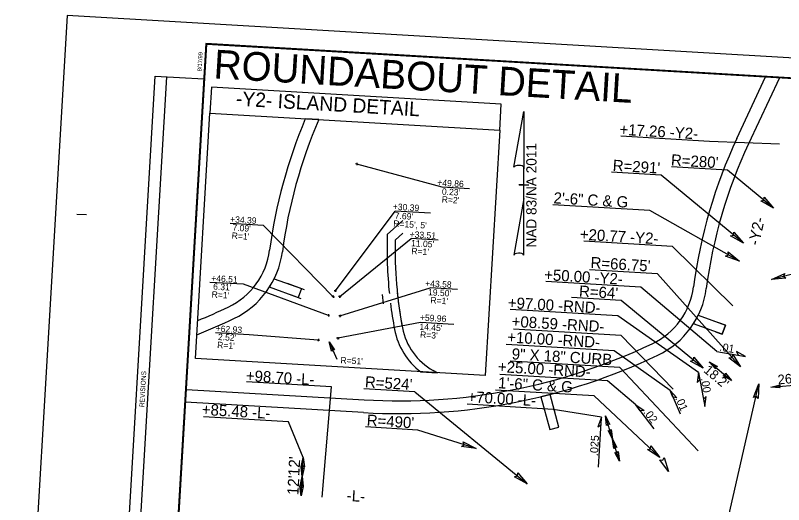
# Model space of a CAD drawing. Extents: x 2012744 to 2013625, y 444638 to 445237.
# Drawn here: x 2012743.6 to 2013223.7, y 444930.6 to 445236.8 of the extents above; entities that cross this region are included whole.
import ezdxf

# ---------------------------------------------------------------- set-up
doc = ezdxf.new("R2010")
doc.units = 0
for name, color, linetype in [('Old_Level_1', 7, 'Continuous'), ('Old_Level_10', 7, 'Continuous'), ('Prop Conc 4in Sidewalk', 7, 'Continuous'), ('Prop Dimension', 7, 'Continuous'), ('Prop Dimension Text', 7, 'Continuous'), ('Prop North Arrow NAD83 for Plan Sheets CELL', 7, 'Continuous'), ('Prop Shade Medium', 7, 'Continuous'), ('Prop Superelevation  Arrow CELL', 7, 'Continuous'), ('Prop Superelevation Label', 7, 'Continuous'), ('Prop Terminator CELL', 7, 'Continuous'), ('Sheet Block Revision CELL', 7, 'Continuous'), ('Sheet Clip Boundary CELL', 7, 'Continuous'), ('Sheet Plan And Profile CELL', 7, 'Continuous'), ('Sheet Plot Border Outside CELL', 7, 'Continuous')]:
    doc.layers.add(name, color=color, linetype=linetype)

msp = doc.modelspace()

# ---------------------------------------------------------------- linework, layer by layer
at = {"layer": 'Old_Level_1'}
for points in [[(2012865.22, 445175.54), (2013046.27, 445164.87), (2013047.24, 445181.2), (2012866.19, 445191.87)], [(2012865.22, 445175.54), (2013046.27, 445164.87), (2013037.11, 445011.37), (2012856.18, 445022.04)]]:
    msp.add_lwpolyline(points, close=True, dxfattribs=at)
at = {"layer": 'Prop Conc 4in Sidewalk'}
for p, q in [((2012924.35, 445065.12), (2012913.57, 445069.04)), ((2012922.29, 445059.48), (2012916.22, 445061.69))]:
    msp.add_line(p, q, dxfattribs=at)
for centre, radius, start, end in [((2013249.36, 445090.83), 268.5, 185.8936, 190.6549), ((2013249.36, 445090.83), 273.5, 187.1616, 190.6549), ((2013023.33, 445048.31), 38.5, 190.6549, 241.0711)]:
    msp.add_arc(centre, radius, start, end, dxfattribs=at)
at = {"layer": 'Prop Dimension'}
for p, q in [((2013177.31, 445157.92), (2013122.04, 445161.18)), ((2013010.35, 445129.33), (2012956.94, 445143.77)), ((2013188.68, 445139.96), (2013153.65, 445142.03)), ((2013147.07, 445136.87), (2013116.07, 445138.7)), ((2013027.37, 445128.32), (2013010.35, 445129.33)), ((2013140.05, 445114.63), (2013079.38, 445118.21)), ((2012943.61, 445064.49), (2012980.9, 445114.25)), ((2013002.96, 445112.95), (2012980.9, 445114.25)), ((2013196.1, 445083.05), (2013140.05, 445114.63)), ((2012898.72, 445105.32), (2012877.76, 445106.55)), ((2012942.24, 445060.77), (2012898.72, 445105.32)), ((2012946.3, 445060.82), (2012990.86, 445097.07)), ((2013007.88, 445096.07), (2012990.86, 445097.07)), ((2013154.21, 445092.18), (2013098.94, 445095.44)), ((2013285.84, 445089.12), (2013216.04, 445071.62)), ((2013144.93, 445075.13), (2013102.29, 445077.64)), ((2012886.17, 445068.5), (2012865.21, 445069.73)), ((2013134.55, 445066.74), (2013075.06, 445070.25)), ((2012939.27, 445049.09), (2012886.17, 445068.5)), ((2012946.44, 445048.74), (2013002.78, 445066.29)), ((2013019.8, 445065.29), (2013002.78, 445066.29)), ((2013122.16, 445058.44), (2013091.16, 445060.27)), ((2013120.13, 445048.71), (2013052.78, 445052.68)), ((2012996.72, 445044.68), (2012945.12, 445034.71)), ((2013017.68, 445043.45), (2012996.72, 445044.68)), ((2012889.65, 445036.94), (2012868.68, 445038.17)), ((2012932.89, 445033.62), (2012889.65, 445036.94)), ((2013122.22, 445036.51), (2013054.85, 445040.48)), ((2012939.67, 445032.45), (2012944.53, 445021.69)), ((2013117.77, 445026.79), (2013050.4, 445030.76)), ((2013121.35, 445016.42), (2013052.8, 445020.46)), ((2013177.2, 445020.08), (2013191.14, 445008.35)), ((2013113.63, 445008.18), (2013046.25, 445012.15)), ((2013121.35, 445016.42), (2013170.22, 444964.22)), ((2012941.18, 445004.29), (2012888.11, 445007.42)), ((2012935.33, 444935.42), (2012941.18, 445004.29)), ((2012993.31, 445001.15), (2012961.38, 445003.03)), ((2013105.33, 444998.67), (2013043.63, 445002.31)), ((2013168.27, 444830.65), (2013208.29, 445006.14)), ((2013215.66, 445004.13), (2013241.81, 445006.46)), ((2012993.31, 445001.15), (2013063.53, 444943.63)), ((2013146.23, 444960.14), (2013105.33, 444998.67)), ((2013079.64, 444990.26), (2013026.04, 444993.42)), ((2012914.27, 444982.56), (2012861.2, 444985.69)), ((2013116.76, 444971.71), (2013112.3, 444986.13)), ((2012923.55, 444960.15), (2012914.27, 444982.56)), ((2012995.09, 444977.35), (2012962.33, 444979.28)), ((2013031.55, 444965.74), (2012995.09, 444977.35)), ((2013121.03, 444957.92), (2013116.76, 444971.71)), ((2012922.84, 444948.17), (2012923.55, 444960.15)), ((2012922.14, 444936.19), (2012922.84, 444948.17))]:
    msp.add_line(p, q, dxfattribs=at)
at = {"layer": 'Prop Dimension Text'}
for p, q in [((2013221.16, 445156.24), (2013177.31, 445157.92)), ((2012956.94, 445143.77), (2012956.19, 445143.81)), ((2012956.99, 445144.51), (2012956.9, 445143.02)), ((2012956.94, 445143.77), (2012957.69, 445143.72)), ((2013198.55, 445094.22), (2013147.07, 445136.87)), ((2013217.44, 445116.14), (2013188.68, 445139.96)), ((2013191.92, 445054.96), (2013154.21, 445092.18)), ((2013196.73, 445016.84), (2013144.93, 445075.13)), ((2012943.65, 445065.24), (2012943.56, 445063.74)), ((2013181.94, 445026.49), (2013134.55, 445066.74)), ((2012942.24, 445060.77), (2012941.49, 445060.82)), ((2012942.29, 445061.52), (2012942.2, 445060.02)), ((2012942.24, 445060.77), (2012942.99, 445060.73)), ((2012943.61, 445064.49), (2012942.86, 445064.53)), ((2012943.61, 445064.49), (2012944.36, 445064.45)), ((2012946.3, 445060.82), (2012945.55, 445060.86)), ((2012946.34, 445061.57), (2012946.25, 445060.07)), ((2012946.3, 445060.82), (2012947.05, 445060.77)), ((2013173.42, 445015.97), (2013122.16, 445058.44)), ((2012939.27, 445049.09), (2012938.52, 445049.13)), ((2012939.31, 445049.84), (2012939.22, 445048.34)), ((2012939.27, 445049.09), (2012940.02, 445049.05)), ((2012946.44, 445048.74), (2012945.69, 445048.79)), ((2012946.48, 445049.49), (2012946.39, 445047.99)), ((2012946.44, 445048.74), (2012947.19, 445048.7)), ((2013170.51, 445013.24), (2013120.13, 445048.71)), ((2013154.65, 445003), (2013122.22, 445036.51)), ((2012932.89, 445033.62), (2012932.14, 445033.66)), ((2012932.94, 445034.36), (2012932.85, 445032.87)), ((2012932.89, 445033.62), (2012933.64, 445033.57)), ((2012945.12, 445034.71), (2012944.37, 445034.75)), ((2012945.16, 445035.45), (2012945.07, 445033.96)), ((2012945.12, 445034.71), (2012945.87, 445034.66)), ((2013152.69, 445002.12), (2013117.77, 445026.79)), ((2013131.25, 444993.12), (2013113.63, 445008.18)), ((2013109.87, 444985.3), (2013079.64, 444990.26))]:
    msp.add_line(p, q, dxfattribs=at)
at = {"layer": 'Prop North Arrow NAD83 for Plan Sheets CELL'}
for p, q in [((2013055.17, 445141.81), (2013061.32, 445176.58)), ((2013061.36, 445176.58), (2013061.32, 445176.58)), ((2013061.36, 445176.58), (2013061.32, 445176.58)), ((2013061.36, 445176.58), (2013061.36, 445140.73)), ((2013061.35, 445122.13), (2013061.36, 445141.78)), ((2013061.36, 445140.73), (2013061.36, 445141.74)), ((2013058.36, 445130.83), (2013058.32, 445130.83)), ((2013061.02, 445130.83), (2013058.36, 445130.83)), ((2013058.39, 445130.83), (2013064.39, 445130.83)), ((2013061.35, 445122.13), (2013055.09, 445086.69)), ((2013061.39, 445086.84), (2013061.35, 445122.13))]:
    msp.add_line(p, q, dxfattribs=at)
for centre, start_param, end_param in [((2013058.27, 445141.44), 0.216388, 2.908219), ((2013058.27, 445086.56), 0.201328, 3.141593)]:
    msp.add_ellipse(centre, major_axis=(3.17, -0.02), ratio=0.461098, start_param=start_param, end_param=end_param, dxfattribs=at)
at = {"layer": 'Prop Shade Medium'}
for p, q in [((2013194.49, 445159.8), (2013212.46, 445198.27)), ((2013221.05, 445197.76), (2013201.74, 445156.41)), ((2012933.31, 445171.53), (2012924.82, 445172.03)), ((2012985.73, 445108.41), (2012976.01, 445099.74)), ((2012980.91, 445096.05), (2012985.8, 445100.47)), ((2012902.41, 445066.72), (2012905.39, 445072.02)), ((2012905.39, 445072.02), (2012922.51, 445065.79)), ((2012920.45, 445060.15), (2012902.41, 445066.72)), ((2012922.47, 445065.8), (2012920.41, 445060.17)), ((2012972.85, 445062.19), (2012973.53, 445056.23)), ((2013167.32, 445043.81), (2013170.31, 445049.11)), ((2013170.31, 445049.11), (2013187.43, 445042.87)), ((2013187.38, 445042.89), (2013178.49, 445046.13)), ((2013185.37, 445037.24), (2013167.32, 445043.81)), ((2013185.33, 445037.25), (2013187.38, 445042.89)), ((2013187.38, 445042.89), (2013185.33, 445037.25)), ((2013181.14, 445038.78), (2013185.33, 445037.25)), ((2012996.91, 445013.74), (2013007.39, 445013.13)), ((2013007.39, 445013.13), (2013004.7, 445014.61)), ((2012850.01, 444994.79), (2012850.48, 445002.78)), ((2012850.48, 445002.78), (2012961.67, 444996.22)), ((2013077.77, 444999.64), (2013071.95, 444998.18)), ((2013071.95, 444998.18), (2013077.53, 444977.62)), ((2013083.32, 444979.2), (2013077.77, 444999.64)), ((2012961.2, 444988.24), (2012850.01, 444994.79)), ((2013077.54, 444977.62), (2013083.32, 444979.2))]:
    msp.add_line(p, q, dxfattribs=at)
for centre, radius, start, end in [((2013215.86, 445048.95), 316, 157.0774, 172.5631), ((2013215.86, 445048.95), 308, 156.548, 172.5631), ((2013480.78, 445026.04), 316, 154.9563, 172.5631), ((2013480.78, 445026.04), 308, 154.9563, 172.5631), ((2013249.36, 445090.83), 273.5, 178.1336, 185.9047), ((2013249.36, 445090.83), 268.5, 178.8864, 190.6549), ((2012856.91, 445095.81), 46, 295.4749, 352.5631), ((2012856.91, 445095.81), 54, 295.4749, 352.5631), ((2013121.83, 445072.89), 46, 295.4749, 352.5631), ((2013121.83, 445072.89), 54, 295.4749, 352.5631), ((2013249.36, 445090.83), 273.5, 187.1616, 190.6549), ((2012718.41, 445386.5), 368, 292.2205, 295.4749), ((2012718.41, 445386.5), 376, 291.638, 295.4749), ((2013023.33, 445048.31), 38.5, 190.6549, 241.0711), ((2013023.33, 445048.31), 43.5, 190.6549, 232.6121), ((2012983.33, 445363.58), 368, 266.6264, 295.4749), ((2012983.33, 445363.58), 376, 266.6264, 295.4749)]:
    msp.add_arc(centre, radius, start, end, dxfattribs=at)
at = {"layer": 'Prop Superelevation  Arrow CELL'}
for points in [[(2013199.91, 445023.41), (2013194.34, 445026.39), (2013195.35, 445024.19)], [(2013170.51, 445013.24), (2013169.65, 445006.98), (2013171.36, 445008.7)], [(2013152.69, 445002.12), (2013156.88, 444997.38), (2013154.5, 444997.86)], [(2013174.47, 444992.11), (2013175.33, 444998.38), (2013173.61, 444996.66)], [(2013131.25, 444993.12), (2013136.48, 444989.56), (2013134.06, 444989.44)], [(2013109.87, 444985.3), (2013107.52, 444979.43), (2013109.6, 444980.68)]]:
    msp.add_lwpolyline(points, close=True, dxfattribs=at)
at = {"layer": 'Prop Superelevation Label'}
for p, q in [((2013181.94, 445026.49), (2013199.91, 445023.41)), ((2013170.51, 445013.24), (2013174.47, 444992.11)), ((2013152.69, 445002.12), (2013158.94, 444987.42)), ((2013142.78, 444978.02), (2013131.25, 444993.12)), ((2013108.03, 444954.08), (2013109.87, 444985.3))]:
    msp.add_line(p, q, dxfattribs=at)
at = {"layer": 'Prop Terminator CELL'}
for points in [[(2013211.5, 445123.07), (2013217.44, 445116.14), (2013209.45, 445120.68), (2013211.36, 445121.18)], [(2013192.61, 445101.16), (2013198.55, 445094.22), (2013190.56, 445098.76), (2013192.47, 445099.26)], [(2013189.02, 445088.82), (2013196.1, 445083.05), (2013187.43, 445086.1), (2013189.21, 445086.93)], [(2013225.14, 445072.31), (2013216.04, 445071.62), (2013224.43, 445075.37), (2013223.7, 445073.54)], [(2012941.16, 445026.7), (2012939.67, 445032.45), (2012943.04, 445027.51), (2012941.79, 445027.77)], [(2013167.48, 445022.91), (2013173.42, 445015.97), (2013165.43, 445020.52), (2013167.34, 445021.01)], [(2013191.91, 445024.6), (2013196.73, 445016.84), (2013189.52, 445022.54), (2013191.48, 445022.74)], [(2013181.03, 445015.55), (2013177.2, 445020.08), (2013182.37, 445017.09), (2013181.13, 445016.78)], [(2013187.32, 445012.89), (2013191.14, 445008.35), (2013185.97, 445011.34), (2013187.21, 445011.66)], [(2013204.78, 444997.71), (2013208.29, 445006.14), (2013207.84, 444996.96), (2013206.53, 444998.44)], [(2013221.58, 445003.65), (2013215.66, 445004.13), (2013221.43, 445005.69), (2013220.78, 445004.59)], [(2013113.07, 444980.25), (2013112.3, 444986.13), (2013115.04, 444980.82), (2013113.82, 444981.23)], [(2013116, 444977.6), (2013116.76, 444971.71), (2013114.03, 444977.03), (2013115.25, 444976.62)], [(2013023.44, 444969.95), (2013031.55, 444965.74), (2013022.44, 444966.96), (2013024.02, 444968.14)], [(2013117.53, 444965.83), (2013116.76, 444971.71), (2013119.5, 444966.4), (2013118.28, 444966.81)], [(2013120.27, 444963.8), (2013121.03, 444957.92), (2013118.3, 444963.23), (2013119.52, 444962.82)], [(2013140.75, 444967.44), (2013146.23, 444960.14), (2013138.55, 444965.18), (2013140.48, 444965.56)], [(2012922.2, 444954.37), (2012923.55, 444960.15), (2012924.24, 444954.22), (2012923.25, 444955.03)], [(2013149.07, 444960.16), (2013151.75, 444951.42), (2013146.24, 444958.78), (2013148.18, 444958.47)], [(2012924.19, 444953.95), (2012922.84, 444948.17), (2012922.15, 444954.11), (2012923.14, 444953.3)], [(2013057.55, 444950.54), (2013063.53, 444943.63), (2013055.52, 444948.13), (2013057.42, 444948.64)], [(2012921.49, 444942.39), (2012922.84, 444948.17), (2012923.53, 444942.24), (2012922.54, 444943.05)], [(2012923.49, 444941.97), (2012922.14, 444936.19), (2012921.44, 444942.13), (2012922.44, 444941.32)]]:
    msp.add_lwpolyline(points, close=True, dxfattribs=at)
at = {"layer": 'Sheet Block Revision CELL'}
msp.add_line((2012815.07, 444803.74), (2012838.34, 445198.38), dxfattribs=at)
msp.add_lwpolyline([(2012807.81, 444804.17), (2012831.07, 445198.81), (2012861.3, 445197.03), (2012838.03, 444802.39)], close=True, dxfattribs=at)
at = {"layer": 'Sheet Clip Boundary CELL'}
for points in [[(2013605.95, 445084.18), (2013506.09, 445090.07), (2013509.49, 445147.63), (2013409.64, 445153.51), (2013411.6, 445186.8), (2012862.6, 445219.16), (2012831.71, 444695.07), (2013580.41, 444650.94)], [(2012832.37, 444695.56), (2012863.22, 445218.85), (2013411.41, 445186.54), (2013409.45, 445153.34), (2013509.31, 445147.45), (2013505.92, 445089.85), (2013605.86, 445083.96), (2013580.34, 444651.05)]]:
    msp.add_lwpolyline(points, close=True, dxfattribs=at)
at = {"layer": 'Sheet Plan And Profile CELL'}
msp.add_line((2012781.93, 445112.48), (2012788.17, 445112.11), dxfattribs=at)
msp.add_lwpolyline([(2013611.3, 445175.03), (2012862.6, 445219.16), (2012831.71, 444695.07), (2013580.41, 444650.94)], close=True, dxfattribs=at)
at = {"layer": 'Sheet Plot Border Outside CELL'}
msp.add_lwpolyline([(2012743.62, 444687.74), (2013592.15, 444637.73), (2013624.51, 445186.77), (2012775.99, 445236.79)], close=True, dxfattribs=at)

# ---------------------------------------------------------------- texts
at = {"layer": 'Old_Level_10'}
for s, p in [('+49.86', (2013007.21, 445130.24)), ("0.23'", (2013010.06, 445124.63)), ("R=2'", (2013009.97, 445119.68)), ('+30.39', (2012979.4, 445115.2)), ("7.69'", (2012980.6, 445109.55)), ('+34.39', (2012877.74, 445107.28)), ("R=15', 5'", (2012979.67, 445104.58)), ("7.09'", (2012879.19, 445102.05)), ("R=1'", (2012878.71, 445097.03)), ('+33.51', (2012989.9, 445097.86)), ("11.05'", (2012990.8, 445092.36)), ("R=1'", (2012990.96, 445087.4)), ('+46.51', (2012865.94, 445070.42)), ('+43.58', (2012999.63, 445067.2)), ("6.31'", (2012867.12, 445065.2)), ("19.50'", (2013001.39, 445061.66)), ("R=1'", (2012866.16, 445060.2)), ("R=1'", (2013002.88, 445056.62)), ('+59.96', (2012996.33, 445045.86)), ('+62.93', (2012868.72, 445038.9)), ("14.45'", (2012995.99, 445039.97)), ("2.52'", (2012870.12, 445033.67)), ("R=3'", (2012996.41, 445035.12)), ("R=1'", (2012869.63, 445028.64)), ("R=51'", (2012946.68, 445019.1))]:
    msp.add_text(s, height=4, rotation=356.6264, dxfattribs=at).set_placement(p)
at = {"layer": 'Prop Dimension'}
for s, height, rotation, p in [('ROUNDABOUT DETAIL', 18, 356.6264, (2012867.2, 445197.41)), ('-Y2- ISLAND DETAIL', 9, 356.6264, (2012881.27, 445180.34)), ('-Y2- ', 7, 77.6645, (2013208.25, 445092.43)), ('-L-', 7, 356.6264, (2012950.54, 444932.96))]:
    msp.add_text(s, height=height, rotation=rotation, dxfattribs=at).set_placement(p)
at = {"layer": 'Prop Dimension Text'}
for s, height, rotation, p in [('+17.26 -Y2-', 7, 356.6264, (2013120.96, 445162.09)), ("R=291'", 7, 356.6264, (2013116.75, 445139.51)), ("R=280'", 7, 356.6264, (2013153.15, 445142.91)), ('2\'-6" C & G', 7, 356.6264, (2013079.76, 445119.18)), ('+20.77 -Y2-', 7, 356.6264, (2013096.19, 445096.45)), ("R=66.75'", 7, 356.6264, (2013102.88, 445078.71)), ('+50.00 -Y2-', 7, 356.6264, (2013073.91, 445071.16)), ("R=64'", 7, 356.6264, (2013095.69, 445060.85)), ('+97.00 -RND-', 7, 356.6264, (2013051.19, 445053.63)), ('+08.59 -RND-', 7, 356.6264, (2013053.61, 445041.93)), ('+10.00 -RND-', 7, 356.6264, (2013050.83, 445032.11)), ('9" X 18" CURB ', 7, 356.6264, (2013053.65, 445021.56)), ('+25.00 -RND-', 7, 356.6264, (2013045.02, 445013.61)), ("18.2'", 6, 319.9206, (2013173.24, 445013.98)), ('+98.70 -L-', 7, 356.6264, (2012887.49, 445007.95)), ("26.2'", 6, 5.1016, (2013220.27, 445005.84)), ("R=524'", 7, 356.6264, (2012961.92, 445004.05)), ('1\'-6" C & G', 7, 356.6264, (2013045.11, 445003.49)), ('+70.00 -L-', 7, 356.6264, (2013025.97, 444994.8)), ('+85.48 -L-', 7, 356.6264, (2012859.97, 444986.84)), ("R=490'", 7, 356.6264, (2012963.03, 444980.09)), ("12'", 7, 86.6264, (2012921.01, 444948.37)), ("12'", 7, 86.6264, (2012920.45, 444936.47))]:
    msp.add_text(s, height=height, rotation=rotation, dxfattribs=at).set_placement(p)
at = {"layer": 'Prop North Arrow NAD83 for Plan Sheets CELL'}
msp.add_text('NAD 83/NA 2011', height=6.375, rotation=89.9922, dxfattribs=at).set_placement((2013069.24, 445091.5))
at = {"layer": 'Prop Superelevation Label'}
for s, rotation, p in [('.01', 350.2539, (2013183.33, 445027.05)), ('.00', 278.7035, (2013172.02, 445009.55)), ('.01', 293.0274, (2013155.87, 444997.22)), ('.02', 307.3514, (2013135.78, 444988.42)), ('.025', 86.6264, (2013107.6, 444960.96))]:
    msp.add_text(s, height=5, rotation=rotation, dxfattribs=at).set_placement(p)
at = {"layer": 'Sheet Block Revision CELL'}
msp.add_text('REVISIONS', height=3, rotation=86.6264, dxfattribs=at).set_placement((2012824.12, 444991.61))
at = {"layer": 'Sheet Plan And Profile CELL'}
msp.add_text('8/17/99', height=2.625, rotation=86.6264, dxfattribs=at).set_placement((2012859.94, 445201.69))

doc.saveas('drawing.dxf')
